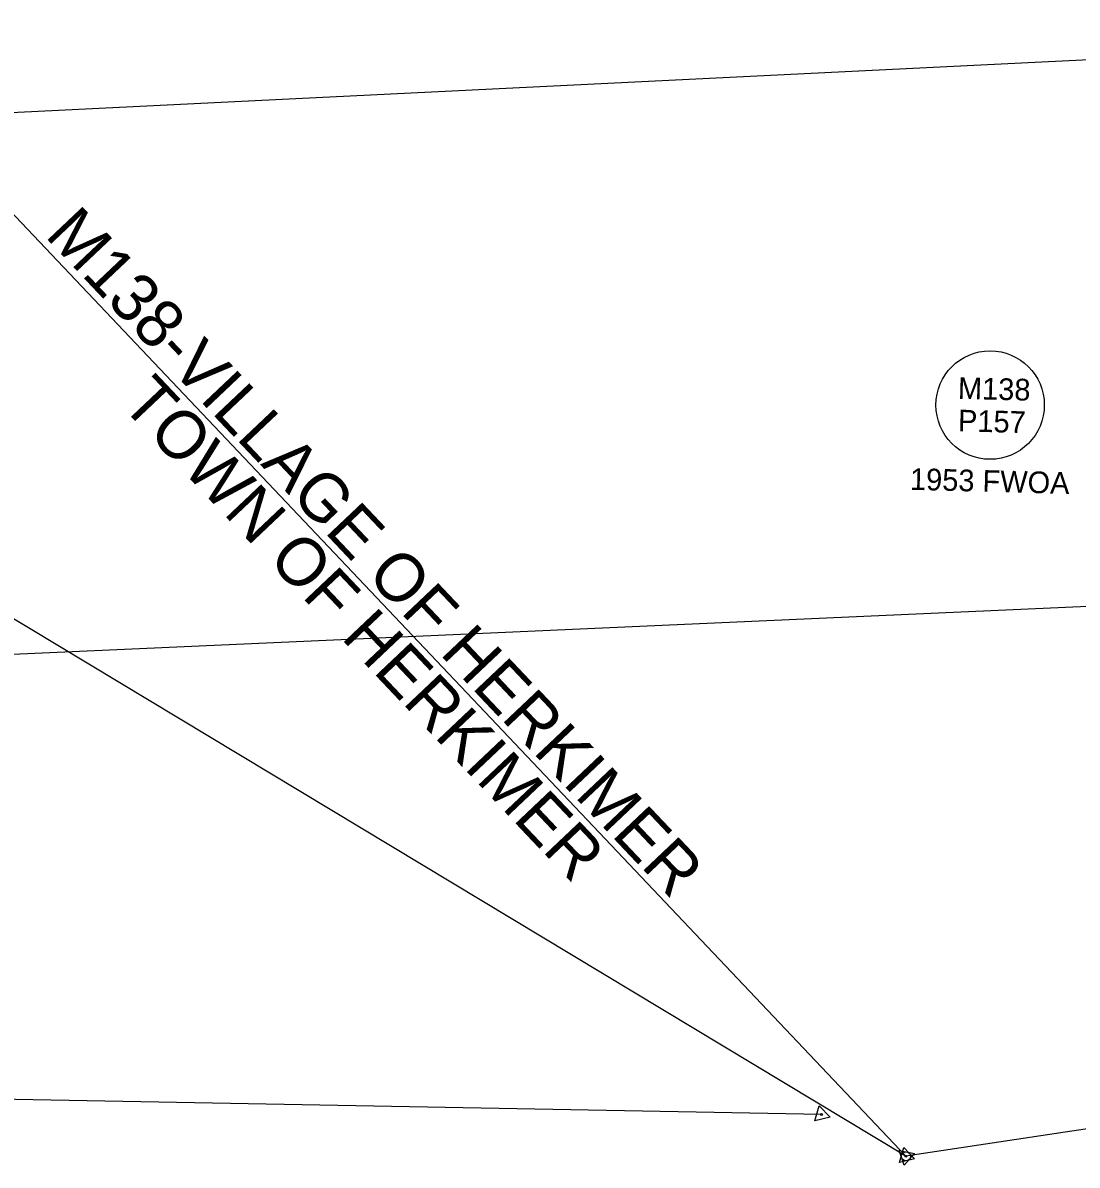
# Model space of a CAD drawing. Extents: x 325029 to 414988, y 1517527 to 1550420.
# Drawn here: x 359376.9 to 359632.1, y 1524591.5 to 1524867.9 of the extents above; entities that cross this region are included whole.
import ezdxf

# ---------------------------------------------------------------- set-up
doc = ezdxf.new("R2010")
doc.units = 0
for name, color, linetype in [('Level 56', 7, 'Continuous'), ('MEE', 7, 'Continuous'), ('MHBWOA', 7, 'Continuous'), ('MJT', 7, 'Continuous'), ('MRBL2', 7, 'Continuous'), ('NNSH_P_T', 7, 'Continuous')]:
    doc.layers.add(name, color=color, linetype=linetype)

msp = doc.modelspace()

# ---------------------------------------------------------------- linework, layer by layer
at = {"layer": 'Level 56'}
msp.add_circle((359611.08, 1524775.39), 13.12, dxfattribs=at)
at = {"layer": 'MEE'}
msp.add_line((359570.24, 1524603.72), (359305.03, 1524608.69), dxfattribs=at)
for points in [[(359568.66, 1524602.21), (359569.71, 1524605.84)], [(359569.71, 1524605.84), (359572.33, 1524603.12)], [(359572.33, 1524603.12), (359568.66, 1524602.21)]]:
    msp.add_lwpolyline(points, dxfattribs=at)
msp.add_circle((359570.24, 1524603.72), 0.227, dxfattribs=at)
at = {"layer": 'MHBWOA'}
for p, q in [((359186.52, 1524836.94), (359815.77, 1524867.87)), ((359590.71, 1524593.62), (359186.52, 1524836.94)), ((359806.47, 1524626.22), (359590.71, 1524593.62))]:
    msp.add_line(p, q, dxfattribs=at)
for points in [[(359590.28, 1524591.49), (359589.07, 1524595.06)], [(359589.07, 1524595.06), (359592.77, 1524594.33)], [(359592.77, 1524594.33), (359590.28, 1524591.49)]]:
    msp.add_lwpolyline(points, dxfattribs=at)
msp.add_circle((359590.71, 1524593.62), 0.227, dxfattribs=at)
at = {"layer": 'MJT'}
msp.add_line((359590.71, 1524593.62), (359352.32, 1524845.09), dxfattribs=at)
for points in [[(359589.12, 1524592.12), (359590.2, 1524595.74)], [(359590.2, 1524595.74), (359592.8, 1524593)], [(359592.8, 1524593), (359589.12, 1524592.12)]]:
    msp.add_lwpolyline(points, dxfattribs=at)
msp.add_circle((359590.7, 1524593.62), 1.09, dxfattribs=at)
at = {"layer": 'MRBL2'}
msp.add_line((357681.26, 1524640), (360124.37, 1524748.44), dxfattribs=at)

# ---------------------------------------------------------------- texts
at = {"layer": 'Level 56'}
for s, p in [('M138', (359603.23, 1524776.91)), ('P157', (359603.25, 1524769.04)), ('1953 FWOA', (359591.62, 1524754.89))]:
    msp.add_text(s, height=5.249, rotation=358.4907, dxfattribs=at).set_placement(p)
at = {"layer": 'NNSH_P_T'}
for s, p in [('M138-VILLAGE OF HERKIMER', (359382.04, 1524816.29)), ('TOWN OF HERKIMER', (359400.35, 1524775.49))]:
    msp.add_text(s, height=11.6264, rotation=313.4096, dxfattribs=at).set_placement(p)

doc.saveas('drawing.dxf')
